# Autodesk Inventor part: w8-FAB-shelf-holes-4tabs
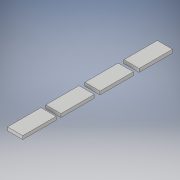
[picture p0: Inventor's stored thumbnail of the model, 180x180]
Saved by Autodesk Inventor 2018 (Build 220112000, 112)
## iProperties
Created: 2018-03
Part Number: w8-FAB-shelf-holes-4tabs
Material: Generic
Document SubType Name: Modeling
Designer: katin
Density: 1 g/cm^3
Appearance: Default
Author: katin
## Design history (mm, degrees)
sketch "Sketch1"
  geometry: L1 (0, 0)-(-50, 0); L2 (-50, 0)-(-50, -110); L3 (-50, -110)-(0, -110); L4 (0, -110)-(0, 0); L5 (0, -125.412)-(-50, -125.412); L6 (-50, -125.412)-(-50, -235.412); L7 (-50, -235.412)-(0, -235.412); L8 (0, -235.412)-(0, -125.412); L9 (0, -254)-(-50, -254); L10 (-50, -254)-(-50, -364); L11 (-50, -364)-(0, -364); L12 (0, -364)-(0, -254); L13 (0, -382.587)-(-50, -382.587); L14 (-50, -382.587)-(-50, -492.587); L15 (-50, -492.587)-(0, -492.587); L16 (0, -492.587)-(0, -382.587)
  constraints: 32 end point, 8 parallel, 5 point on line, 4 horizontal, 4 perpendicular
  dimensions: "d0" = 50 distance of L3.end L2.end; "d1" = 110 distance of L2.end L1.end; "d2" = 50 distance of L7.end L6.end; "d3" = 110 distance of L6.end L5.end; "d4" = 110 distance of L10.end L9.end; "d5" = 110 distance of L14.end L13.end
extrude "Extrusion1" new body sketch "Sketch1" distance "d6" = 11; taper "d7" = 0 deg
body "Solid1"
